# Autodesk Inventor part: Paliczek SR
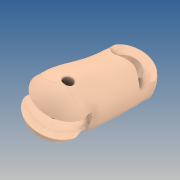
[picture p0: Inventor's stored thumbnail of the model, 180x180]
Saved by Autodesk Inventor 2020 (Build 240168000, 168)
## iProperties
Created: 2019-10
Part Number: Paliczek SR
Material: GFRP
Document SubType Name: Modeling
Designer: yello
Density: 1.75 g/cm^3
Appearance: Default
Author: yello
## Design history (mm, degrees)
feature "Paliczek SR"
sketch "Sketch1"
  geometry: C1 r 2 at (0, 0); 1 further point
  constraints: 1 centre point
  dimensions: "d0" = 4 diameter of C1
extrude "Extrusion1" cut sketch "Sketch1" stored distance "d1" = 100; taper "d2" = 0 deg
sketch "Sketch2"
  geometry: C1 r 5 at (0, 0); 1 further point
  constraints: 1 centre point
  dimensions: "d3" = 10 diameter of C1
extrude "Extrusion2" cut sketch "Sketch2" distance "d4" = 8; taper "d5" = 0 deg
body "Solid1"
